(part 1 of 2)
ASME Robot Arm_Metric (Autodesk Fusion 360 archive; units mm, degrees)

design "ASME Robot Arm - Metric" references "Broached Hexagon Socket Head Cap Screw ASME B18.3.1M - M5x0.8 x 8 Steel Grade 2 Plain"
sketch "Sketch1" plane through (0, 0, 0) normal (0, 1, 0) x axis (1, 0, 0)
  line L1 (125, 0) -> (0, 0)
  line L2 (0, -40) -> (0, 0)
  line L3 (125, -15) -> (125, 0)
  line L4 (115, -15) -> (125, -15)
  line L5 (60, -45) -> (60, -40)
  curve K1 (115, -15) -> (60, -40)
  line L6 (55, -40) -> (60, -40)
  line L7 (55, -33) -> (55, -40)
  line L8 (54, -33) -> (55, -33)
  line L9 (54, -28) -> (54, -33)
  line L10 (55, -28) -> (54, -28)
  line L11 (55, -15.5519) -> (55, -28)
  line L12 (64, -8) -> (55, -15.5519)
  line L13 (64, 0) -> (64, -8)
  point P1 (0, 0)
  point P2 (0, 0)
  point P4 (0, 0)
  point P5 (0, -40)
  point P8 (60, -40)
  point P17 (64, 0)
  point P3 (125, 0)
  point P6 (125, -15)
  point P7 (115, -15)
  point P9 (60, -45)
  point P10 (55, -40)
  point P11 (55, -33)
  point P12 (54, -33)
  point P13 (54, -28)
  point P16 (64, -8)
  coincident P1 P2
  horizontal L1
  coincident P1 P4
  perpendicular L1 L2
  perpendicular L1 L3
  perpendicular L3 L4
  horizontal P5 P8
  perpendicular L5 L6
  perpendicular L6 L7
  perpendicular L7 L8
  perpendicular L8 L9
  perpendicular L9 L10
  perpendicular L4 L11
  coincident L1 P17
  perpendicular L1 L13
  collinear L7 L11
  dimension "d2" distance P4 P5 = 40
  dimension "d3" = 250
  dimension "d4" distance P3 P6 = 15
  dimension "d5" distance P6 P7 = 10
  dimension "d9" distance P8 P9 = 5
  dimension "d16" = 120
  dimension "d17" distance P8 P10 = 5
  dimension "d18" distance P10 P11 = 7
  dimension "d19" distance P12 P13 = 5
  dimension "d20" distance P16 P17 = 8
  dimension "d21" = 128
  dimension "d22" angle L12 L13 = 50
  dimension "d23" = 108
revolve "Revolve1" sketch "Sketch1" AlongAngle 360
sketch "Sketch2" plane through (0, 0, 40) normal (0, 0, 1) x axis (-1, 0, 0)
  line L1 (0, 100) -> (0, 0)
  circle C1 centre (0, 0) radius 30
  circle C2 centre (0, 0) radius 25
  circle C3 centre (0, 0) radius 60
  circle C4 centre (0, 0) radius 55
  point P2 (0, 0)
  point P3 (0, 100)
  vertical L1
  dimension "d8" distance P2 P3 = 100
hole "Hole1" HoleDiameter 9 TipAngle 118 CBDepth 33 CBDiameter 15
circular_pattern "C-Pattern1" TotalAngle 360
sketch "Sketch1" plane through (0, 0, 0) normal (1, 0, 0) x axis (0, 1, 0)
sketch "Sketch2" plane through (0, 0, 0) normal (1, 0, 0) x axis (0, 1, 0)
  line L1 (0, 225) -> (0, 0)
  line L2 (-55, 40) -> (55, 40)
  line L3 (-55, 181.6987) -> (-55, 40)
  curve K1 (-55, 145) -> (-70, 225)
  curve K2 (-53.2004, 137.205) -> (-56.7996, 152.795)
  curve K3 (-70, 217) -> (-70, 233)
  curve K4 (55, 145) -> (70, 225)
  curve K5 (70, 217) -> (70, 233)
  curve K6 (53.2004, 137.205) -> (56.7996, 152.795)
  line L4 (55, 145) -> (-55, 145)
  circle C1 centre (0, 225) radius 70
  point P1 (0, 0)
  point P2 (0, 0)
  point P3 (0, 225)
  point P6 (0, 225)
  point P5 (-55, 40)
  point P7 (-55, 40)
  point P8 (-55, 181.6987)
  point P9 (-70, 225)
  point P10 (-55, 145)
  point P15 (70, 225)
  point P16 (55, 145)
  point P11 (-56.7996, 152.795)
  point P19 (56.7996, 152.795)
  point P12 (-53.2004, 137.205)
  point P20 (53.2004, 137.205)
  point P13 (-70, 233)
  point P17 (70, 233)
  point P14 (-70, 217)
  point P18 (70, 217)
  coincident P1 P2
  vertical L1
  coincident P3 P6
  coincident P5 P7
  coincident C1 P8
  perpendicular L2 L3
  coincident C1 P9
  coincident L3 P10
  midpoint P10 K2
  midpoint P9 K3
  vertical K3
  horizontal P6 P9
  symmetric L1 P9 P15
  symmetric L1 P10 P16
  symmetric L1 P11 P19
  symmetric L1 P12 P20
  symmetric L1 P13 P17
  symmetric L1 P14 P18
  dimension "d24" distance P3 L2 = 185
  dimension "d25" diameter C1 = 140
  dimension "d26" distance P11 P12 = 16
  dimension "d27" distance P13 P14 = 16
  dimension "d28" distance P6 P10 = 80
  dimension "d31" angle L3 K2 = 13
extrude "Extrude1" new body sketch "Sketch2" profile of C1 K1 K4 L4 distance 130
work_plane "WorkPlane1" AlongDistance 5
sketch "Sketch3" plane through (0, 0, 45) normal (0, 0, 1) x axis (-1, 0, 0)
  circle C1 centre (0, 0) radius 60
  circle C2 centre (0, 0) radius 55
  circle C3 centre (0, 0) radius 60
loft "Loft1" sketch "Sketch3" Start TakeOff Angle 0
sketch "Sketch4" plane through (0, 0, 0) normal (0, 1, 0) x axis (1, 0, 0)
  line L1 (65, -295) -> (-65, -295)
  line L2 (30, -295) -> (-30, -295)
  line L3 (30, -153) -> (30, -295)
  line L4 (-30, -153) -> (30, -153)
  line L5 (-30, -295) -> (-30, -153)
  line L6 (0, -153) -> (0, -295)
  point P4 (-30, -295)
  point P8 (0, -295)
  point P9 (0, -153)
  point P6 (30, -153)
  point P7 (-30, -153)
  point P10 (65, -225)
  horizontal L2
  vertical L3
  horizontal L4
  vertical L5
  coincident L1 P4
  midpoint L1 P8
  midpoint L4 P9
  midpoint L1 L2
  dimension "d36" distance P6 P7 = 60
  dimension "d37" distance L4 P10 = 72
extrude "Extrude2" cut sketch "Sketch4" profile of L1 L2 L3 L4 L5 no distance stored
as_built_joint "As-built1" OffsetX 0 OffsetY 0 OffsetZ 0 AngleZ 0
sketch "Sketch1" plane through (0, 0, 0) normal (1, 0, 0) x axis (0, 1, 0)
  line L1 (0, 575) -> (0, 225)
  curve K1 (46.9846, 557.899) -> (63.4415, 254.5833)
  curve K2 (63.4408, 254.5848) -> (63.4423, 254.5817)
  curve K3 (48.4834, 566.399) -> (45.4858, 549.399)
  line L2 (46.9846, 557.899) -> (0, 575)
  line L3 (50, 575) -> (0, 575)
  line L4 (63.4415, 254.5833) -> (0, 225)
  curve K4 (-46.9846, 557.899) -> (-63.4415, 254.5833)
  curve K5 (-63.4408, 254.5848) -> (-63.4423, 254.5817)
  curve K6 (-48.4834, 566.399) -> (-45.4858, 549.399)
  line L5 (46.9846, 557.899) -> (-46.9846, 557.899)
  line L6 (63.4415, 254.5833) -> (-63.4415, 254.5833)
  arc A1 centre (0, 225) radius 70 clockwise from (-70, 225) to (70, 225)
  circle C1 centre (0, 225) radius 70
  circle C2 centre (0, 575) radius 50
  point P2 (70, 225)
  point P5 (0, 225)
  point P6 (0, 225)
  point P8 (63.4415, 254.5833)
  point P9 (46.9846, 557.899)
  point P14 (0, 575)
  point P15 (46.9846, 557.899)
  point P16 (0, 575)
  point P17 (0, 575)
  point P18 (50, 575)
  point P4 (0, 225)
  point P19 (0, 225)
  point P7 (0, 575)
  point P10 (63.4423, 254.5817)
  point P20 (-63.4415, 254.5833)
  point P21 (-46.9846, 557.899)
  point P22 (-63.4423, 254.5817)
  point P11 (63.4408, 254.5848)
  point P23 (-63.4408, 254.5848)
  point P12 (45.4858, 549.399)
  point P24 (-45.4858, 549.399)
  point P13 (48.4834, 566.399)
  point P25 (-48.4834, 566.399)
  concentric A1 C1
  coincident P2 C1
  coincident P5 P6
  vertical L1
  coincident A1 P8
  midpoint P8 K2
  midpoint P9 K3
  vertical P5 P14
  coincident C2 P15
  coincident P14 P16
  coincident P14 P17
  coincident C2 P18
  horizontal L3
  tangent C1 K2
  coincident P4 P19
  coincident P7 P14
  coincident P9 C2
  coincident K3 P15
  coincident A1 P10
  coincident C1 P10
  symmetric L1 P8 P20
  symmetric L1 P9 P21
  symmetric L1 P10 P22
  symmetric L1 P11 P23
  symmetric L1 P12 P24
  symmetric L1 P13 P25
  dimension "d50" diameter C2 = 100
  dimension "d51" distance P5 P14 = 350
  dimension "d52" angle L2 L3 = 20
  dimension "d54" angle L1 L4 = 65
  dimension "d55" angle K3 L3 = 80
  dimension "d56" distance P12 P13 = 17
extrude "Extrude1" new body sketch "Sketch1" profile of C1 distance 29
extrude "Extrude2" new body sketch "Sketch1" profile of C2 distance 45
split_face "SplitFace1"
split_face "SplitFace2"
sketch "Sketch2" plane through (0, 0, 0) normal (0, 1, 0) x axis (1, 0, 0)
  line L1 (29, -295) -> (-29, -295)
  line L2 (-22.5, -525) -> (22.5, -525)
  curve K1 (22.5, -525) -> (29, -295)
  line L3 (0, -557.2354) -> (0, -225)
  curve K2 (22.5, -547.5) -> (22.5, -502.5)
  curve K3 (29, -317.5) -> (29, -272.5)
  curve K4 (-22.5, -525) -> (-29, -295)
  curve K5 (-29, -317.5) -> (-29, -272.5)
  curve K6 (-22.5, -547.5) -> (-22.5, -502.5)
  point P3 (29, -295)
  point P6 (29, -295)
  point P4 (22.5, -525)
  point P7 (22.5, -525)
  point P8 (0, -225)
  point P9 (0, -225)
  point P15 (-29, -295)
  point P16 (-22.5, -525)
  point P11 (22.5, -502.5)
  point P19 (-22.5, -502.5)
  point P12 (22.5, -547.5)
  point P20 (-22.5, -547.5)
  point P13 (29, -272.5)
  point P17 (-29, -272.5)
  point P14 (29, -317.5)
  point P18 (-29, -317.5)
  coincident P3 P6
  coincident P4 P7
  coincident P8 P9
  perpendicular L2 L3
  midpoint P7 K2
  vertical K2
  midpoint P6 K3
  vertical K3
  symmetric P6 L3 P15
  symmetric P7 L3 P16
  symmetric L3 P11 P19
  symmetric L3 P12 P20
  symmetric L3 P13 P17
  symmetric L3 P14 P18
  dimension "d59" distance P11 P12 = 45
  dimension "d60" distance P13 P14 = 45
loft "Loft1"
as_built_joint "As-built2" OffsetX 0 OffsetY 0 OffsetZ 0 AngleZ 0 RotateMinimum -107 RotateMaximum 107
sketch "Sketch1" plane through (0, 0, 0) normal (1, 0, 0) x axis (0, 1, 0)
  line L1 (0, 925) -> (0, 575)
  line L2 (45.3154, 596.1309) -> (0, 575)
  line L3 (36.2222, 915.2943) -> (0, 925)
  curve K1 (36.2222, 915.2943) -> (45.3154, 596.1309)
  curve K2 (42.2511, 937.7943) -> (30.1934, 892.7943)
  curve K3 (34.8235, 618.6309) -> (55.8073, 573.6309)
  curve K4 (-36.2222, 915.2943) -> (-45.3154, 596.1309)
  curve K5 (-34.8235, 618.6309) -> (-55.8073, 573.6309)
  curve K6 (-42.2511, 937.7943) -> (-30.1934, 892.7943)
  line L4 (-45.3154, 596.1309) -> (45.3154, 596.1309)
  line L5 (-36.2222, 915.2943) -> (36.2222, 915.2943)
  arc A1 centre (0, 575) radius 50 clockwise from (-46.9846, 557.899) to (46.9846, 557.899)
  circle C1 centre (0, 575) radius 50
  circle C2 centre (0, 925) radius 37.5
  point P2 (46.9846, 557.899)
  point P4 (0, 575)
  point P7 (0, 575)
  point P6 (0, 925)
  point P8 (0, 925)
  point P9 (0, 575)
  point P10 (45.3154, 596.1309)
  point P11 (0, 925)
  point P12 (36.2222, 915.2943)
  point P17 (-45.3154, 596.1309)
  point P18 (-36.2222, 915.2943)
  point P13 (30.1934, 892.7943)
  point P21 (-30.1934, 892.7943)
  point P14 (42.2511, 937.7943)
  point P22 (-42.2511, 937.7943)
  point P15 (55.8073, 573.6309)
  point P19 (-55.8073, 573.6309)
  point P16 (34.8235, 618.6309)
  point P20 (-34.8235, 618.6309)
  point P5 (0, 575)
  concentric A1 C1
  coincident P2 C1
  coincident P4 P7
  coincident P6 P8
  vertical L1
  coincident P4 P9
  coincident C1 P10
  coincident P6 P11
  coincident C2 P12
  midpoint P12 K2
  midpoint P10 K3
  symmetric L1 P10 P17
  symmetric L1 P12 P18
  symmetric L1 P13 P21
  symmetric L1 P14 P22
  symmetric L1 P15 P19
  symmetric L1 P16 P20
  tangent C1 K3
  tangent C2 K2
  dimension "d65" diameter C2 = 75
  dimension "d66" distance P5 P6 = 350
  dimension "d67" angle L1 L2 = 65
  dimension "d68" angle L1 L3 = 75
  dimension "d71" distance P13 P14 = 45
  dimension "d72" distance P15 P16 = 45
extrude "Extrude1" new body sketch "Sketch1" profile of C1 L4 distance 100
extrude "Extrude2" new body sketch "Sketch1" profile of C2 L5 distance 80
sketch "Sketch2" plane through (0, 0, 0) normal (0, 1, 0) x axis (1, 0, 0)
  line L1 (-50, -625) -> (-50, -525)
  line L2 (-40, -962.5) -> (-40, -887.5)
  curve K1 (-40, -887.5) -> (-50, -625)
  curve K2 (-40, -915) -> (-40, -860)
  curve K3 (-50, -652.5) -> (-50, -597.5)
  line L3 (0, -911.4032) -> (0, -575)
  curve K4 (40, -887.5) -> (50, -625)
  curve K5 (50, -652.5) -> (50, -597.5)
  curve K6 (40, -915) -> (40, -860)
  line L4 (0, -915.2943) -> (0, -596.1309)
  point P3 (-50, -625)
  point P6 (-50, -625)
  point P4 (-40, -887.5)
  point P7 (-40, -887.5)
  point P12 (0, -575)
  point P13 (0, -575)
  point P15 (50, -625)
  point P16 (40, -887.5)
  point P8 (-40, -860)
  point P19 (40, -860)
  point P9 (-40, -915)
  point P20 (40, -915)
  point P10 (-50, -597.5)
  point P17 (50, -597.5)
  point P11 (-50, -652.5)
  point P18 (50, -652.5)
  coincident P3 P6
  coincident P4 P7
  midpoint P7 K2
  midpoint P6 K3
  coincident P12 P13
  vertical L3
  symmetric P6 L3 P15
  symmetric P7 L3 P16
  symmetric P8 L3 P19
  symmetric P9 L3 P20
  symmetric P10 L3 P17
  symmetric P11 L3 P18
  vertical K3
  vertical K2
  dimension "d77" distance P8 P9 = 55
  dimension "d78" distance P10 P11 = 55
split_face "SplitFace1"
split_face "SplitFace2"
work_plane "WorkPlane1" RotateAngle 0
work_plane "WorkPlane2" AlongDistance 40
sketch "Sketch4" plane through (0, 0, 847.5) normal (0, 0, -1) x axis (-1, 0, 0)
  circle C1 centre (0, 0) radius 42.5
  point P1 (0, 0)
  point P2 (0, 0)
  coincident P1 P2
  dimension "d92" diameter C1 = 85
loft "Loft2" sketch "Sketch4"
sketch "Sketch1" plane through (0, 0, 0) normal (1, 0, 0) x axis (0, 1, 0)
  line L1 (0, 925) -> (0, 575)
  line L2 (45.3154, 596.1309) -> (0, 575)
  line L3 (36.2222, 915.2943) -> (0, 925)
  curve K1 (36.2222, 915.2943) -> (45.3154, 596.1309)
  curve K2 (42.2511, 937.7943) -> (30.1934, 892.7943)
  curve K3 (37.1261, 618.6309) -> (53.5047, 573.6309)
  curve K4 (-36.2222, 915.2943) -> (-45.3154, 596.1309)
  curve K5 (-37.1261, 618.6309) -> (-53.5047, 573.6309)
  curve K6 (-42.2511, 937.7943) -> (-30.1934, 892.7943)
  line L4 (-45.3154, 596.1309) -> (45.3154, 596.1309)
  line L5 (-36.2222, 915.2943) -> (36.2222, 915.2943)
  arc A1 centre (0, 575) radius 50 clockwise from (-46.9846, 557.899) to (46.9846, 557.899)
  circle C1 centre (0, 575) radius 50
  circle C2 centre (0, 925) radius 37.5
  point P2 (46.9846, 557.899)
  point P4 (0, 575)
  point P7 (0, 575)
  point P6 (0, 925)
  point P8 (0, 925)
  point P9 (0, 575)
  point P10 (45.3154, 596.1309)
  point P11 (0, 925)
  point P12 (36.2222, 915.2943)
  point P17 (-45.3154, 596.1309)
  point P18 (-36.2222, 915.2943)
  point P13 (30.1934, 892.7943)
  point P21 (-30.1934, 892.7943)
  point P14 (42.2511, 937.7943)
  point P22 (-42.2511, 937.7943)
  point P15 (53.5047, 573.6309)
  point P19 (-53.5047, 573.6309)
  point P16 (37.1261, 618.6309)
  point P20 (-37.1261, 618.6309)
  point P5 (0, 575)
  concentric A1 C1
  coincident P2 C1
  coincident P4 P7
  coincident P6 P8
  vertical L1
  coincident P4 P9
  coincident C1 P10
  coincident P6 P11
  coincident C2 P12
  midpoint P12 K2
  midpoint P10 K3
  symmetric L1 P10 P17
  symmetric L1 P12 P18
  symmetric L1 P13 P21
  symmetric L1 P14 P22
  symmetric L1 P15 P19
  symmetric L1 P16 P20
  dimension "d65_1" diameter C2 = 75
  dimension "d66_1" distance P5 P6 = 350
  dimension "d67_1" angle L1 L2 = 65
  dimension "d68_1" angle L1 L3 = 75
  dimension "d69_1" angle L2 K3 = 85
  dimension "d70_1" angle L1 K2 = 15
  dimension "d71_1" distance P13 P14 = 45
  dimension "d72_1" distance P15 P16 = 45
extrude "Extrude1" new body sketch "Sketch1" profile of C1 L4 distance 100 named "d73_1"
extrude "Extrude2" new body sketch "Sketch1" profile of C2 L5 distance 80 named "d75_1"
sketch "Sketch2" plane through (0, 0, 0) normal (0, 1, 0) x axis (1, 0, 0)
  line L1 (-50, -625) -> (-50, -525)
  line L2 (-40, -962.5) -> (-40, -887.5)
  curve K1 (-40, -887.5) -> (-50, -625)
  curve K2 (-47.1175, -914.063) -> (-32.8825, -860.937)
  curve K3 (-42.8825, -651.563) -> (-57.1175, -598.437)
  line L3 (0, -911.4032) -> (0, -575)
  curve K4 (40, -887.5) -> (50, -625)
  curve K5 (42.8825, -651.563) -> (57.1175, -598.437)
  curve K6 (47.1175, -914.063) -> (32.8825, -860.937)
  line L4 (0, -915.2943) -> (0, -596.1309)
  point P3 (-50, -625)
  point P6 (-50, -625)
  point P4 (-40, -887.5)
  point P7 (-40, -887.5)
  point P12 (0, -575)
  point P13 (0, -575)
  point P15 (50, -625)
  point P16 (40, -887.5)
  point P8 (-32.8825, -860.937)
  point P19 (32.8825, -860.937)
  point P9 (-47.1175, -914.063)
  point P20 (47.1175, -914.063)
  point P10 (-57.1175, -598.437)
  point P17 (57.1175, -598.437)
  point P11 (-42.8825, -651.563)
  point P18 (42.8825, -651.563)
  coincident P3 P6
  coincident P4 P7
  midpoint P7 K2
  midpoint P6 K3
  coincident P12 P13
  vertical L3
  symmetric P6 L3 P15
  symmetric P7 L3 P16
  symmetric P8 L3 P19
  symmetric P9 L3 P20
  symmetric P10 L3 P17
  symmetric P11 L3 P18
  dimension "d77_1" distance P8 P9 = 55
  dimension "d78_1" distance P10 P11 = 55
  dimension "d79_1" angle K3 L4 = 15
  dimension "d80_1" angle K2 L4 = 15
split_face "SplitFace1"
split_face "SplitFace2"
work_plane "WorkPlane1" RotateAngle 0 named "d91_1"
work_plane "WorkPlane2" AlongDistance 40 named "d93_1"
sketch "Sketch4" plane through (0, 0, 847.5) normal (0, 0, -1) x axis (-1, 0, 0)
  circle C1 centre (0, 0) radius 42.5
  point P1 (0, 0)
  point P2 (0, 0)
  coincident P1 P2
  dimension "d92_1" diameter C1 = 85
extrude "Extrude4" new body sketch "Sketch4" against normal blind 5
loft "Loft2"
loft "Loft1"
sketch "Sketch3" plane through (0, 0, 0) normal (0, 1, 0) x axis (1, 0, 0)
  line L1 (-50, -525) -> (50, -525)
  line L2 (40, -962.5) -> (-40, -962.5)
  line L3 (-23, -525) -> (23, -525)
  line L4 (-23, -630) -> (-23, -525)
  line L5 (23, -630) -> (-23, -630)
  line L6 (23, -525) -> (23, -630)
  line L7 (-19, -962.5) -> (19, -962.5)
  line L8 (-19, -886.5) -> (-19, -962.5)
  line L9 (19, -886.5) -> (-19, -886.5)
  line L10 (19, -962.5) -> (19, -886.5)
  point P6 (23, -525)
  point P10 (19, -962.5)
  point P8 (-23, -630)
  point P9 (23, -630)
  point P7 (-23, -525)
  point P11 (-19, -962.5)
  point P12 (-19, -886.5)
  horizontal L3
  vertical L4
  horizontal L5
  vertical L6
  coincident L1 P6
  midpoint L1 L3
  horizontal L7
  vertical L8
  horizontal L9
  vertical L10
  coincident L2 P10
  midpoint L2 L7
  dimension "d81" distance P8 P9 = 46
  dimension "d82" distance P7 P8 = 105
  dimension "d83" distance P10 P11 = 38
  dimension "d84" distance P11 P12 = 76
extrude "Extrude3" cut sketch "Sketch3" distance 150
remove_body "RemoveBody1"
as_built_joint "As-built3" OffsetX 0 OffsetY 0 OffsetZ 0 AngleZ 0 RotateMinimum -105 RotateMaximum 105
sketch "Sketch3" plane through (0, 0, 0) normal (0, 1, 0) x axis (1, 0, 0)
  line L1 (-50, -525) -> (50, -525)
  line L2 (40, -962.5) -> (-40, -962.5)
  line L3 (-23, -525) -> (23, -525)
  line L4 (-23, -630) -> (-23, -525)
  line L5 (23, -630) -> (-23, -630)
  line L6 (23, -525) -> (23, -630)
  line L7 (-19, -962.5) -> (19, -962.5)
  line L8 (-19, -886.5) -> (-19, -962.5)
  line L9 (19, -886.5) -> (-19, -886.5)
  line L10 (19, -962.5) -> (19, -886.5)
  point P6 (23, -525)
  point P10 (19, -962.5)
  point P8 (-23, -630)
  point P9 (23, -630)
  point P7 (-23, -525)
  point P11 (-19, -962.5)
  point P12 (-19, -886.5)
  horizontal L3
  vertical L4
  horizontal L5
  vertical L6
  coincident L1 P6
  midpoint L1 L3
  horizontal L7
  vertical L8
  horizontal L9
  vertical L10
  coincident L2 P10
  midpoint L2 L7
  dimension "d81_1" distance P8 P9 = 46
  dimension "d82_1" distance P7 P8 = 105
  dimension "d83_1" distance P10 P11 = 38
  dimension "d84_1" distance P11 P12 = 76
extrude "Extrude5" cut sketch "Sketch3" profile of L2 L7 L8 L9 L10 no distance stored
remove_body "RemoveBody1"
as_built_joint "As-built4" OffsetX 0 OffsetY 0 OffsetZ 0 AngleZ 0
sketch "Sketch1" plane through (0, 0, 0) normal (1, 0, 0) x axis (0, 1, 0)
  line L1 (-35.2385, 937.8258) -> (35.2385, 937.8258)
  line L2 (-35.2385, 937.8258) -> (0, 925)
  line L3 (0, 962.5) -> (0, 925)
  arc A1 centre (0, 925) radius 37.5 clockwise from (-36.2222, 915.2943) to (36.2222, 915.2943)
  circle C1 centre (0, 925) radius 37.5
  point P3 (-36.2222, 915.2943)
  point P6 (35.2385, 937.8258)
  point P7 (-35.2385, 937.8258)
  point P5 (0, 925)
  point P8 (0, 925)
  point P9 (-35.2385, 937.8258)
  point P10 (0, 925)
  point P11 (0, 962.5)
  concentric A1 C1
  coincident P3 C1
  coincident A1 P6
  coincident C1 P7
  horizontal L1
  coincident P5 P8
  coincident P7 P9
  coincident P5 P10
  midpoint A1 P11
  dimension "d109" angle L2 L3 = 70
extrude "Extrude1" new body sketch "Sketch1" profile of A1 C1 L1 distance 37.5
work_plane "WorkPlane1" RotateAngle 0
work_plane "WorkPlane2" AlongDistance 50
sketch "Sketch2" plane through (0, 0, 1012.5) normal (0, 0, 1) x axis (1, 0, 0)
  circle C1 centre (0, 0) radius 50
  point P1 (0, 0)
  point P2 (0, 0)
  coincident P1 P2
  dimension "d106" diameter C1 = 100
extrude "Extrude2" new body sketch "Sketch2" along normal blind 10
split_face "SplitFace1"
sketch "Sketch3" plane through (0, 0, 0) normal (0, 1, 0) x axis (1, 0, 0)
  line L1 (-18.75, -962.5) -> (-18.75, -937.8258)
  line L2 (0, -1012.5) -> (0, 0)
  line L3 (50, -1012.5) -> (-50, -1012.5)
  curve K1 (-50, -1012.5) -> (-18.75, -962.5)
  curve K2 (-51.6246, -1017.5) -> (-48.3754, -1007.5)
  curve K3 (-21.9992, -972.5) -> (-15.5008, -952.5)
  curve K4 (50, -1012.5) -> (18.75, -962.5)
  curve K5 (21.9992, -972.5) -> (15.5008, -952.5)
  curve K6 (51.6246, -1017.5) -> (48.3754, -1007.5)
  point P1 (0, 0)
  point P4 (0, 0)
  point P5 (0, -1012.5)
  point P3 (-18.75, -962.5)
  point P8 (-18.75, -962.5)
  point P6 (-50, -1012.5)
  point P9 (-50, -1012.5)
  point P14 (18.75, -962.5)
  point P15 (50, -1012.5)
  point P10 (-48.3754, -1007.5)
  point P18 (48.3754, -1007.5)
  point P11 (-51.6246, -1017.5)
  point P19 (51.6246, -1017.5)
  point P12 (-15.5008, -952.5)
  point P16 (15.5008, -952.5)
  point P13 (-21.9992, -972.5)
  point P17 (21.9992, -972.5)
  coincident P1 P4
  parallel L1 L2
  midpoint P5 L3
  coincident P3 P8
  coincident P6 P9
  midpoint P9 K2
  midpoint P8 K3
  parallel K2 K3
  symmetric L2 P8 P14
  symmetric L2 P9 P15
  symmetric L2 P10 P18
  symmetric L2 P11 P19
  symmetric L2 P12 P16
  symmetric L2 P13 P17
  dimension "d110" angle L2 K3 = 18
  dimension "d111" distance P12 P13 = 20
  dimension "d112" distance P10 P11 = 10
sketch "Sketch4" plane through (0, 0, 0) normal (1, 0, 0) x axis (0, 1, 0)
  line L1 (-50, 1012.5) -> (50, 1012.5)
  curve K1 (50, 1012.5) -> (35.2385, 937.8258)
  curve K2 (35.2385, 945.3258) -> (35.2385, 930.3258)
  curve K3 (53.4973, 1020) -> (46.5027, 1005)
  line L2 (0, 1012.5) -> (0, 962.5)
  line L3 (0, 1012.5) -> (0, 0)
  curve K4 (-50, 1012.5) -> (-35.2385, 937.8258)
  curve K5 (-35.2385, 945.3258) -> (-35.2385, 930.3258)
  curve K6 (-53.4973, 1020) -> (-46.5027, 1005)
  arc A1 centre (0, 925) radius 37.5 clockwise from (-36.2222, 915.2943) to (36.2222, 915.2943)
  point P5 (50, 1012.5)
  point P8 (50, 1012.5)
  point P7 (35.2385, 937.8258)
  point P17 (-35.2385, 937.8258)
  point P18 (-50, 1012.5)
  point P9 (35.2385, 930.3258)
  point P19 (-35.2385, 930.3258)
  point P10 (35.2385, 945.3258)
  point P20 (-35.2385, 945.3258)
  point P11 (46.5027, 1005)
  point P21 (-46.5027, 1005)
  point P12 (53.4973, 1020)
  point P22 (-53.4973, 1020)
  point P23 (35.2385, 937.8258)
  coincident P5 P8
  midpoint P7 K2
  vertical K2
  midpoint P8 K3
  symmetric P7 L3 P17
  symmetric P8 L3 P18
  symmetric P9 L3 P19
  symmetric P10 L3 P20
  symmetric P11 L3 P21
  symmetric P12 L3 P22
  coincident P7 P23
  dimension "d113" angle K3 L2 = 25
  dimension "d115" distance P11 P12 = 15
  dimension "d116" distance P9 P10 = 15
loft "Loft1"
as_built_joint "As-built5" OffsetX 0 OffsetY 0 OffsetZ 0 AngleZ 0 RotateMinimum -92 RotateMaximum 92
sketch "Sketch1" plane through (0, 0, 0) normal (0, 1, 0) x axis (1, 0, 0)
  line L1 (50, -1022.5) -> (-50, -1022.5)
  line L2 (0, -1035.5) -> (0, -1020.5)
  line L3 (-50, -1032.5) -> (-50, -1022.5)
  line L4 (-34, -1032.5) -> (-50, -1032.5)
  line L5 (-34, -1031.5) -> (-34, -1032.5)
  line L6 (-31, -1031.5) -> (-34, -1031.5)
  line L7 (-31, -1032.5) -> (-31, -1031.5)
  line L8 (-27.5, -1032.5) -> (-31, -1032.5)
  line L9 (-27.5, -1035.5) -> (-27.5, -1032.5)
  line L10 (0, -1035.5) -> (-27.5, -1035.5)
  line L11 (-27.5, -1022.5) -> (-50, -1022.5)
  line L12 (-27.5, -1020.5) -> (-27.5, -1022.5)
  line L13 (0, -1020.5) -> (-27.5, -1020.5)
  point P8 (-34, -1032.5)
  point P2 (-50, -1022.5)
  point P6 (-50, -1022.5)
  point P14 (-50, -1022.5)
  point P15 (-27.5, -1022.5)
  point P4 (0, -1020.5)
  point P17 (0, -1020.5)
  point P18 (0, -1022.5)
  point P12 (-27.5, -1032.5)
  point P5 (0, -1035.5)
  point P9 (-34, -1031.5)
  point P10 (-31, -1031.5)
  point P16 (-27.5, -1020.5)
  perpendicular L1 L2
  perpendicular L1 L3
  perpendicular L3 L4
  perpendicular L4 L5
  perpendicular L5 L6
  perpendicular L6 L7
  perpendicular L5 L8
  perpendicular L8 L9
  perpendicular L2 L10
  coincident P8 L8
  coincident P2 L3
  coincident P2 P6
  coincident P2 P14
  coincident L1 P15
  perpendicular L3 L11
  perpendicular L1 L12
  perpendicular L12 L13
  coincident P4 P17
  midpoint L1 P18
  coincident L2 P18
  coincident P12 L12
  dimension "d121" distance P4 P5 = 15
  dimension "d123" distance P9 P10 = 3
  dimension "d124" distance P8 P9 = 1
  dimension "d125" = 62
  dimension "d126" = 55
  dimension "d167" distance L1 L4 = 10
  dimension "d169" distance P15 P16 = 2
revolve "Revolve1" sketch "Sketch1" AlongAngle 360
sketch "Sketch2" plane through (0, 0, 1032.5) normal (0, 0, 1) x axis (-1, 0, 0)
  line L1 (0, 41) -> (0, 0)
  circle C1 centre (0, 0) radius 34
  circle C2 centre (0, 0) radius 50
  point P2 (0, 0)
  point P3 (0, 0)
  point P4 (0, 41)
  coincident P2 P3
  vertical L1
  dimension "d128" distance P3 P4 = 41
hole "Hole1" HoleDepth 20 HoleDiameter 5.5 TipAngle 180 CBDepth 5 CBDiameter 10
circular_pattern "C-Pattern1" TotalAngle 360
sketch "Sketch3" plane through (0, 0, 1035.5) normal (0, 0, 1) x axis (-1, 0, 0)
  line L1 (0, 20) -> (0, 0)
  line L2 (8.4853, 8.4853) -> (0, 0)
  line L3 (10, 0) -> (0, 0)
  circle C1 centre (0, 0) radius 27.5
  point P2 (0, 0)
  point P3 (0, 0)
  point P5 (0, 0)
  point P4 (0, 20)
  point P6 (8.4853, 8.4853)
  coincident P2 P3
  vertical L1
  horizontal L3
  coincident P2 P5
  dimension "d136" distance P3 P4 = 20
  dimension "d137" distance P5 P6 = 12
  dimension "d138" angle L2 L3 = 45
hole "Hole1" HoleDepth 20 HoleDiameter 4.234 TipAngle 180
circular_pattern "C-Pattern2" TotalAngle 360
hole "Hole2" HoleDepth 20 HoleDiameter 4.234 TipAngle 180
as_built_joint "As-built6" OffsetX 0 OffsetY 0 OffsetZ 0 AngleZ 0
extrude "Extrude3" add of existing geometry to an object
sketch "Sketch5" plane through (0, 0, 0) normal (0, 1, 0) x axis (1, 0, 0)
  line L1 (0, -1022.5) -> (0, -1017.5)
  line L2 (-50, -1022.5) -> (50, -1022.5)
  line L3 (27.55, -1017.5) -> (0, -1017.5)
  line L4 (27.55, -1022.5) -> (27.55, -1017.5)
  line L5 (0, -1022.5) -> (27.55, -1022.5)
  point P3 (0, -1022.5)
  point P7 (27.55, -1022.5)
  point P2 (0, -1017.5)
  vertical L1
  midpoint P3 L2
  perpendicular L1 L3
  coincident L2 P7
  perpendicular L2 L4
  dimension "d170" distance P2 P3 = 5
  dimension "d171" = 55.1
revolve "Revolve1" sketch "Sketch5" AlongAngle 360
sketch "Sketch6" plane through (0, 0, 1022.5) normal (0, 0, 1) x axis (-1, 0, 0)
  circle C1 centre (0, 0) radius 27.55
  circle C2 centre (0, 0) radius 50
  circle C3 centre (0, 41) radius 2.75
hole "Hole3" HoleDepth 15 HoleDiameter 4.234 TipAngle 180
circular_pattern "C-Pattern1" TotalAngle 360
chamfer "Chamfer1" distance 3 distance 1 distance 0.5
fillet "Fillet1" radius 3
fillet "Fillet2" radius 35
fillet "Fillet1" radius 8 15
fillet "Fillet1" radius 200 10
sketch "Sketch3" plane through (0, 0, 0) normal (1, 0, 0) x axis (0, 1, 0)
  line L1 (0, 490) -> (0, 340)
  curve K1 (24.1481, 483.5295) -> (33.8074, 349.0587)
  line L2 (33.8074, 349.0587) -> (0, 340)
  curve K2 (24.8557, 497.0295) -> (23.4406, 470.0295)
  line L3 (24.1481, 483.5295) -> (0, 490)
  curve K3 (-24.1481, 483.5295) -> (-33.8074, 349.0587)
  curve K4 (32.2112, 362.0587) -> (35.4036, 336.0587)
  curve K5 (-32.2112, 362.0587) -> (-35.4036, 336.0587)
  curve K6 (-24.8557, 497.0295) -> (-23.4406, 470.0295)
  circle C1 centre (0, 490) radius 25
  circle C2 centre (0, 340) radius 35
  arc A1 centre (0, 225) radius 70 clockwise from (-70, 225) to (70, 225)
  point P3 (0, 340)
  point P4 (0, 340)
  point P2 (0, 490)
  point P5 (0, 490)
  point P1 (0, 0)
  point P9 (33.8074, 349.0587)
  point P10 (24.1481, 483.5295)
  point P11 (0, 340)
  point P14 (0, 490)
  point P15 (-33.8074, 349.0587)
  point P16 (-24.1481, 483.5295)
  point P12 (23.4406, 470.0295)
  point P21 (-23.4406, 470.0295)
  point P13 (24.8557, 497.0295)
  point P22 (-24.8557, 497.0295)
  point P17 (35.4036, 336.0587)
  point P19 (-35.4036, 336.0587)
  point P18 (32.2112, 362.0587)
  point P20 (-32.2112, 362.0587)
  point P8 (0, 225)
  coincident P3 P4
  coincident P2 P5
  vertical L1
  coincident P1 L1
  coincident C2 P9
  coincident C1 P10
  coincident P3 P11
  midpoint P10 K2
  coincident P2 P14
  midpoint P9 K4
  symmetric L1 P9 P15
  symmetric L1 P10 P16
  symmetric L1 P12 P21
  symmetric L1 P13 P22
  symmetric L1 P17 P19
  symmetric L1 P18 P20
  dimension "d196" diameter C2 = 70
  dimension "d197" diameter C1 = 50
  dimension "d198" distance P3 P8 = 115
  dimension "d199" distance P4 P5 = 150
  dimension "d200" angle L1 L2 = 75
  dimension "d201" angle L1 L3 = 75
  dimension "d202" angle L1 K2 = 3
  dimension "d203" angle L1 K4 = 7
  dimension "d204" distance P17 P18 = 26
  dimension "d205" distance P12 P13 = 27
extrude "Extrude3" sketch "Sketch3" profile of C1 C2 K1 K3 blind 5
mirror "Mirror1" mirrorStitchTolerance 0.1
fillet "Fillet2" radius 120
chamfer "Chamfer1" distance 2
sketch "Sketch5" plane through (65, 0, 0) normal (1, 0, 0) x axis (0, 1, 0)
  curve K1 (39.6152, 145) -> (40.3844, 148.3743)
  curve K2 (40.3844, 148.3743) -> (55, 225)
  curve K3 (-55, 225) -> (-40.3844, 148.3743)
  curve K4 (-40.3844, 148.3743) -> (-39.6152, 145)
  line L1 (39.6152, 145) -> (-39.6152, 145)
  arc A1 centre (0, 225) radius 55 clockwise from (-55, 225) to (55, 225)
  arc A2 centre (0, 225) radius 55 clockwise from (-55, 225) to (55, 225)
  circle C1 centre (0, 225) radius 55
  point P10 (-55, 225)
  concentric A2 C1
  coincident P10 C1
work_plane "WorkPlane2" sketch "Sketch5" AlongDistance 6
sketch "Sketch6" plane through (71, 0, 0) normal (1, 0, 0) x axis (0, 1, 0)
loft "Loft2" sketch "Sketch5"
mirror "Mirror1" mirrorStitchTolerance 0.1
fillet "Fillet1" radius 10
fillet "Fillet2" radius 100
fillet "Fillet3" radius 10
fillet "Fillet2" radius 10
fillet "Fillet4" radius 10
work_plane "WorkPlane3" AlongDistance 5
sketch "Sketch5" plane through (55, 0, 0) normal (1, 0, 0) x axis (0, 1, 0)
  arc A1 centre (0, 575) radius 50 clockwise from (45.6932, 595.3011) to (-45.6932, 595.3011)
loft "Loft3"
mirror "Mirror1" mirrorStitchTolerance 0.1
fillet "Fillet5" radius 50
fillet "Fillet4" radius 5
sketch "Sketch7" plane through (0, 0, 0) normal (1, 0, 0) x axis (0, 1, 0)
  line L1 (4.1989, 228.3433) -> (-19.0632, 190.9471)
  line L2 (4.1989, 247.7426) -> (4.1989, 228.3433)
  line L3 (-8.9006, 229.9785) -> (2.1114, 248.3458)
  curve K1 (-12.1232, 228.3672) -> (-8.9006, 229.9785)
  line L4 (-19.0632, 228.3486) -> (-12.1232, 228.3672)
  line L5 (-19.0632, 251.6902) -> (-19.0632, 228.3486)
  line L6 (21.2698, 251.6902) -> (-19.0632, 251.6902)
  line L7 (22.7039, 227.9253) -> (22.7039, 250.1979)
  line L8 (-0.4577, 190.6191) -> (22.7039, 227.9253)
  line L9 (-19.0632, 190.6191) -> (-0.4577, 190.6191)
  line L10 (-19.0632, 190.9471) -> (-19.0632, 190.6191)
  line L11 (17.8557, 598.5641) -> (-14.4108, 598.5641)
  line L12 (-14.4108, 549.7072) -> (0.4736, 549.7072)
  line L13 (-14.4108, 549.9697) -> (-14.4108, 549.7072)
  line L14 (19.0029, 579.5522) -> (19.0029, 597.3703)
  line L15 (-14.4108, 579.8909) -> (-8.8588, 579.9057)
  line L16 (-6.2807, 581.1948) -> (2.5289, 595.8887)
  line L17 (4.1989, 595.4061) -> (4.1989, 579.8867)
  line L18 (4.1989, 579.8867) -> (-14.4108, 549.9697)
  line L19 (0.4736, 549.7072) -> (19.0029, 579.5522)
  line L20 (-14.4108, 598.5641) -> (-14.4108, 579.8909)
  curve K2 (-8.8588, 579.9057) -> (-6.2807, 581.1948)
  curve K3 (-7.553, 924.1916) -> (-5.2327, 925.3517)
  line L21 (-12.5498, 940.9841) -> (-12.5498, 924.1782)
  line L22 (-12.5498, 924.1782) -> (-7.553, 924.1916)
  line L23 (-12.5498, 897.2492) -> (-12.5498, 897.0129)
  line L24 (4.1989, 938.1419) -> (4.1989, 924.1744)
  line L25 (17.5225, 923.8734) -> (17.5225, 939.9097)
  line L26 (0.8461, 897.0129) -> (17.5225, 923.8734)
  line L27 (4.1989, 924.1744) -> (-12.5498, 897.2492)
  line L28 (16.49, 940.9841) -> (-12.5498, 940.9841)
  line L29 (-5.2327, 925.3517) -> (2.6959, 938.5762)
  line L30 (-12.5498, 897.0129) -> (0.8461, 897.0129)
  arc A1 centre (3.0665, 247.7426) radius 1.1324 clockwise from (3.0639, 248.875) to (4.1989, 247.7426)
  arc A2 centre (2.9857, 247.8939) radius 0.9843 clockwise from (2.1114, 248.3458) to (3.0639, 248.875)
  arc A3 centre (21.2738, 250.2588) radius 1.4314 clockwise from (21.2698, 251.6902) to (22.7039, 250.1979)
  arc A4 centre (3.2283, 595.5271) radius 0.7874 clockwise from (2.5289, 595.8887) to (3.2909, 596.312)
  arc A5 centre (3.293, 595.4061) radius 0.9059 clockwise from (3.2909, 596.312) to (4.1989, 595.4061)
  arc A6 centre (17.8588, 597.419) radius 1.1451 clockwise from (17.8557, 598.5641) to (19.0029, 597.3703)
  arc A7 centre (16.4928, 939.9535) radius 1.0306 clockwise from (16.49, 940.9841) to (17.5225, 939.9097)
  arc A8 centre (3.3254, 938.2508) radius 0.7087 clockwise from (2.6959, 938.5762) to (3.3817, 938.9572)
  arc A9 centre (3.3836, 938.1419) radius 0.8153 clockwise from (3.3817, 938.9572) to (4.1989, 938.1419)
emboss "Emboss1" sketch "Sketch7" Depth -2 Horizontal Distance 0 Vertical Distance 0 Rotation Angle 0
emboss "Emboss1" sketch "Sketch7" Depth -2 Horizontal Distance 0 Vertical Distance 0 Rotation Angle 0
emboss "Emboss1" sketch "Sketch7" Depth -2 Horizontal Distance 0 Vertical Distance 0 Rotation Angle 0
sketch "Sketch8" plane through (0, 0, 0) normal (1, 0, 0) x axis (0, 1, 0)
  line L1 (4.3387, 213.8621) -> (-18.9234, 251.2583)
  line L2 (4.3387, 194.4628) -> (4.3387, 213.8621)
  line L3 (-8.7608, 212.2269) -> (2.2512, 193.8596)
  curve K1 (-11.9834, 213.8382) -> (-8.7608, 212.2269)
  line L4 (-18.9234, 213.8568) -> (-11.9834, 213.8382)
  line L5 (-18.9234, 190.5152) -> (-18.9234, 213.8568)
  line L6 (21.4097, 190.5152) -> (-18.9234, 190.5152)
  line L7 (22.8437, 214.2801) -> (22.8437, 192.0075)
  line L8 (-0.3179, 251.5863) -> (22.8437, 214.2801)
  line L9 (-18.9234, 251.5863) -> (-0.3179, 251.5863)
  line L10 (-18.9234, 251.2583) -> (-18.9234, 251.5863)
  line L11 (-14.271, 568.4323) -> (-8.719, 568.4175)
  line L12 (19.1427, 568.771) -> (19.1427, 550.9529)
  line L13 (-14.271, 598.616) -> (0.6134, 598.616)
  line L14 (4.3387, 568.4365) -> (-14.271, 598.3535)
  line L15 (-6.1409, 567.1284) -> (2.6687, 552.4345)
  line L16 (-14.271, 598.3535) -> (-14.271, 598.616)
  line L17 (0.6134, 598.616) -> (19.1427, 568.771)
  curve K2 (-8.719, 568.4175) -> (-6.1409, 567.1284)
  line L18 (17.9955, 549.7591) -> (-14.271, 549.7591)
  line L19 (-14.271, 549.7591) -> (-14.271, 568.4323)
  line L20 (4.3387, 552.9171) -> (4.3387, 568.4365)
  line L21 (-12.41, 940.9591) -> (0.9859, 940.9591)
  line L22 (17.6623, 914.0986) -> (17.6623, 898.0623)
  line L23 (-12.41, 940.7228) -> (-12.41, 940.9591)
  line L24 (0.9859, 940.9591) -> (17.6623, 914.0986)
  line L25 (-5.0929, 912.6203) -> (2.8357, 899.3958)
  curve K3 (-7.4132, 913.7804) -> (-5.0929, 912.6203)
  line L26 (-12.41, 913.7938) -> (-7.4132, 913.7804)
  line L27 (4.3387, 899.8301) -> (4.3387, 913.7976)
  line L28 (4.3387, 913.7976) -> (-12.41, 940.7228)
  line L29 (16.6298, 896.9879) -> (-12.41, 896.9879)
  line L30 (-12.41, 896.9879) -> (-12.41, 913.7938)
  arc A1 centre (3.2063, 194.4628) radius 1.1324 between (3.2037, 193.3304) and (4.3387, 194.4628)
  arc A2 centre (3.1255, 194.3115) radius 0.9843 between (2.2512, 193.8596) and (3.2037, 193.3304)
  arc A3 centre (21.4136, 191.9466) radius 1.4314 between (21.4097, 190.5152) and (22.8437, 192.0075)
  arc A4 centre (3.4328, 552.9171) radius 0.9059 between (3.4307, 552.0112) and (4.3387, 552.9171)
  arc A5 centre (3.3682, 552.7961) radius 0.7874 between (2.6687, 552.4345) and (3.4307, 552.0112)
  arc A6 centre (17.9986, 550.9042) radius 1.1451 between (17.9955, 549.7591) and (19.1427, 550.9529)
  arc A7 centre (16.6326, 898.0185) radius 1.0306 between (16.6298, 896.9879) and (17.6623, 898.0623)
  arc A8 centre (3.4652, 899.7212) radius 0.7087 between (2.8357, 899.3958) and (3.5215, 899.0148)
  arc A9 centre (3.5234, 899.8301) radius 0.8153 between (3.5215, 899.0148) and (4.3387, 899.8301)
emboss "Emboss2" sketch "Sketch8" Depth -2 Horizontal Distance 0 Vertical Distance 0 Rotation Angle 0
emboss "Emboss2" sketch "Sketch8" Depth -2 Horizontal Distance 0 Vertical Distance 0 Rotation Angle 0
emboss "Emboss2" sketch "Sketch8" Depth -2 Horizontal Distance 0 Vertical Distance 0 Rotation Angle 0
work_plane "WorkPlane1" AlongDistance 70
sketch "Sketch1" plane through (0, 0, 1105.5) normal (0, 0, 1) x axis (1, 0, 0)
  line L1 (0, -8.7724) -> (0, 0)
  circle C1 centre (17.5, 0) radius 5
  point P1 (0, 0)
  point P2 (0, 0)
  point P4 (17.5, 0)
  coincident P1 P2
  vertical L1
  horizontal P1 P4
  dimension "d264" diameter C1 = 10
  dimension "d265" distance P1 P4 = 17.5 (= "( 35 / 2 ) * 1 mm")
extrude "Extrude1" new body sketch "Sketch1" profile of C1 along normal blind 170 (= "50 mm + 120 mm")
sketch "Sketch2" plane through (0, 0, 1105.5) normal (0, 0, 1) x axis (1, 0, 0)
chamfer "Chamfer1" distance 3 Rotate Angle 75
fillet "Fillet1" radius 1.5 25
work_plane "WorkPlane2" AlongDistance 5.5
sketch "Sketch3" plane through (0, 5.5, 0) normal (0, 1, 0) x axis (1, 0, 0)
  line L1 (22.5, -1105.5) -> (12.5, -1105.5)
  line L2 (17.5, -1130.5) -> (17.5, -1105.5)
  line L3 (12.5, -1155.5) -> (22.5, -1155.5)
  point P4 (17.5, -1105.5)
  point P3 (22.5, -1105.5)
  point P6 (22.5, -1155.5)
  point P2 (12.5, -1105.5)
  point P7 (12.5, -1155.5)
  point P5 (17.5, -1130.5)
  midpoint L1 P4
  perpendicular L1 L2
  horizontal L3
  vertical P3 P6
  vertical P2 P7
  dimension "d274" distance P4 P5 = 25
  dimension "d280" distance L1 L3 = 50
split_face "SplitFace1"
as_built_joint "As-built7"
rectangular_pattern "00000000-0000-0000-0000-000000000000" uSpaceDistance -35 vSpaceDistance 0
sketch "Sketch1" plane through (0, 0, 1105.5) normal (0, 0, -1) x axis (1, 0, 0)
  circle C1 centre (17.5, 0) radius 5
  circle C2 centre (17.5, 0) radius 5
  circle C3 centre (-17.5, 0) radius 5
  circle C4 centre (-17.5, 0) radius 9
  circle C5 centre (17.5, 0) radius 9
  dimension "d285" = 4
  dimension "d286" = 4
extrude "Extrude1" new body sketch "Sketch1" against normal blind 50 bodies "Preserve1", "Preserve2"
sketch "Sketch2" plane through (0, 0, 1035.5) normal (0, 0, 1) x axis (-1, 0, 0)
  circle C1 centre (0, 0) radius 2.117
  circle C2 centre (-14.1421, 14.1421) radius 2.117
  circle C3 centre (0, 12) radius 2.117
  circle C4 centre (-20, 0) radius 2.117
  circle C5 centre (-8.4853, 8.4853) radius 2.117
  circle C6 centre (-14.1421, -14.1421) radius 2.117
  circle C7 centre (-12, 0) radius 2.117
  circle C8 centre (0, -20) radius 2.117
  circle C9 centre (-8.4853, -8.4853) radius 2.117
  circle C10 centre (14.1421, -14.1421) radius 2.117
  circle C11 centre (0, -12) radius 2.117
  circle C12 centre (20, 0) radius 2.117
  circle C13 centre (8.4853, -8.4853) radius 2.117
  circle C14 centre (14.1421, 14.1421) radius 2.117
  circle C15 centre (12, 0) radius 2.117
  circle C16 centre (0, 20) radius 2.117
  circle C17 centre (8.4853, 8.4853) radius 2.117
  circle C18 centre (0, 0) radius 27.5
  circle C19 centre (-14.1421, 14.1421) radius 2.117
  circle C20 centre (-14.1421, -14.1421) radius 2.117
  circle C21 centre (14.1421, -14.1421) radius 2.117
  circle C22 centre (14.1421, 14.1421) radius 2.117
  circle C23 centre (14.1421, -14.1421) radius 5.117
  circle C24 centre (-14.1421, -14.1421) radius 5.117
  circle C25 centre (-14.1421, 14.1421) radius 5.117
  circle C26 centre (14.1421, 14.1421) radius 5.117
  dimension "d289" = 3
  dimension "d290" = 3
  dimension "d291" = 3
  dimension "d292" = 3
extrude "Extrude2" new body sketch "Sketch2" profile of C2 C6 C10 C14 C19 C20 C21 C22 C23 C24 C25 C26 along normal blind 5 bodies "Preserve3", "Preserve4", "Preserve5", "Preserve6"
as_built_joint "As-built1"
extrude "Extrude3" new body sketch "Sketch2" profile of C2 C6 C10 C14 C19 C20 C21 C22 to an object bodies "Obstacle1", "Obstacle2", "Obstacle3", "Obstacle4"
sketch "Sketch4" plane through (0, 0, 1040.5) normal (0, 0, 1) x axis (-1, 0, 0)
  circle C1 centre (14.1421, -14.1421) radius 2.117
  circle C2 centre (14.1421, -14.1421) radius 5.117
  circle C3 centre (14.1421, -14.1421) radius 5.117
  circle C4 centre (-14.1421, -14.1421) radius 5.117
  circle C5 centre (-14.1421, 14.1421) radius 5.117
  circle C6 centre (14.1421, 14.1421) radius 5.117
extrude "Extrude4" add sketch "Sketch4" along normal blind 50
sketch "Sketch5" plane through (0, 0, 1105.5) normal (0, 0, -1) x axis (1, 0, 0)
  circle C1 centre (17.5, 0) radius 5
  circle C2 centre (17.5, 0) radius 9
  circle C3 centre (17.5, 0) radius 9
  circle C4 centre (-17.5, 0) radius 9
extrude "Extrude5" add sketch "Sketch5" along normal blind 5
step "Screw1"
joint "Assemble1" alignAngle 0 alignOffsetX 0 alignOffsetY 0 alignOffsetZ 0
step "Screw2"
joint "Assemble2" alignAngle 0 alignOffsetX 0 alignOffsetY 0 alignOffsetZ 0
step "Screw3"
joint "Assemble3" alignAngle 0 alignOffsetX 0 alignOffsetY 0 alignOffsetZ 0
step "Screw4"
joint "Assemble4" alignAngle 0 alignOffsetX 0 alignOffsetY 0 alignOffsetZ 0
step "Screw5"
joint "Assemble5" alignAngle 0 alignOffsetX 0 alignOffsetY 0 alignOffsetZ 0
step "Screw6"
joint "Assemble6" alignAngle 0 alignOffsetX 0 alignOffsetY 0 alignOffsetZ 0
step "Screw7"
joint "Assemble7" alignAngle 0 alignOffsetX 0 alignOffsetY 0 alignOffsetZ 0
step "Screw8"
joint "Assemble8" alignAngle 0 alignOffsetX 0 alignOffsetY 0 alignOffsetZ 0
sketch "Sketch1" plane through (0, 0, 1105.5) normal (0, 0, -1) x axis (1, 0, 0)
  circle C1 centre (17.5, 0) radius 5
  circle C2 centre (17.5, 0) radius 5
  circle C3 centre (-17.5, 0) radius 5
  circle C4 centre (-17.5, 0) radius 9
  circle C5 centre (17.5, 0) radius 9
  dimension "d285_1" = 4
  dimension "d286_1" = 4
extrude "Extrude1" new body sketch "Sketch1" against normal blind 50 named "d287_1"
sketch "Sketch2" plane through (0, 0, 1035.5) normal (0, 0, 1) x axis (-1, 0, 0)
  circle C1 centre (0, 0) radius 2.117
  circle C2 centre (-14.1421, 14.1421) radius 2.117
  circle C3 centre (0, 12) radius 2.117
  circle C4 centre (-20, 0) radius 2.117
  circle C5 centre (-8.4853, 8.4853) radius 2.117
  circle C6 centre (-14.1421, -14.1421) radius 2.117
  circle C7 centre (-12, 0) radius 2.117
  circle C8 centre (0, -20) radius 2.117
  circle C9 centre (-8.4853, -8.4853) radius 2.117
  circle C10 centre (14.1421, -14.1421) radius 2.117
  circle C11 centre (0, -12) radius 2.117
  circle C12 centre (20, 0) radius 2.117
  circle C13 centre (8.4853, -8.4853) radius 2.117
  circle C14 centre (14.1421, 14.1421) radius 2.117
  circle C15 centre (12, 0) radius 2.117
  circle C16 centre (0, 20) radius 2.117
  circle C17 centre (8.4853, 8.4853) radius 2.117
  circle C18 centre (0, 0) radius 27.5
  circle C19 centre (-14.1421, 14.1421) radius 2.117
  circle C20 centre (-14.1421, -14.1421) radius 2.117
  circle C21 centre (14.1421, -14.1421) radius 2.117
  circle C22 centre (14.1421, 14.1421) radius 2.117
  circle C23 centre (14.1421, -14.1421) radius 5.117
  circle C24 centre (-14.1421, -14.1421) radius 5.117
  circle C25 centre (-14.1421, 14.1421) radius 5.117
  circle C26 centre (14.1421, 14.1421) radius 5.117
  dimension "d289_1" = 3
  dimension "d290_1" = 3
  dimension "d291_1" = 3
  dimension "d292_1" = 3
extrude "Extrude2" new body sketch "Sketch2" profile of C2 C6 C10 C14 C19 C20 C21 C22 C23 C24 C25 C26 along normal blind 5 named "d293_1" bodies "Connection1", "Connection2", "Connection3", "Connection4"
extrude "Extrude3" new body sketch "Sketch2" profile of C2 C6 C10 C14 C19 C20 C21 C22 to an object bodies "Avoid1", "Avoid2", "Avoid3", "Avoid4"
sketch "Sketch4" plane through (0, 0, 1040.5) normal (0, 0, 1) x axis (-1, 0, 0)
  circle C1 centre (14.1421, -14.1421) radius 2.117
  circle C2 centre (14.1421, -14.1421) radius 5.117
  circle C3 centre (14.1421, -14.1421) radius 5.117
  circle C4 centre (-14.1421, -14.1421) radius 5.117
  circle C5 centre (-14.1421, 14.1421) radius 5.117
  circle C6 centre (14.1421, 14.1421) radius 5.117
extrude "Extrude4" add sketch "Sketch4" along normal blind 50 named "d297_1"
sketch "Sketch5" plane through (0, 0, 1105.5) normal (0, 0, -1) x axis (1, 0, 0)
  circle C1 centre (17.5, 0) radius 5
  circle C2 centre (17.5, 0) radius 9
  circle C3 centre (17.5, 0) radius 9
  circle C4 centre (-17.5, 0) radius 9
extrude "Extrude5" add sketch "Sketch5" along normal blind 5 named "d299_1"
position "Position1" RotateAboutZ -98.9 RotateAboutZ 90 RotateAboutZ -23.6 RotateAboutZ 15
as_built_joint "As-built2"
remove_body "RemoveBody10"
remove_body "RemoveBody11"
base_feature "Base Feature"
sketch "Sketch1" plane through (0, 0, 1105.5) normal (0, 0, -1) x axis (1, 0, 0)
  circle C1 centre (17.5, 0) radius 5
  circle C2 centre (17.5, 0) radius 5
  circle C3 centre (-17.5, 0) radius 5
  circle C4 centre (-17.5, 0) radius 9
  circle C5 centre (17.5, 0) radius 9
  dimension "d285_2" = 4
  dimension "d286_2" = 4
  dimension "d343" OffsetThickness = 2
  dimension "d344" OffsetBlendDistance = 0.872
sketch "Sketch2" plane through (0, 0, 1035.5) normal (0, 0, 1) x axis (-1, 0, 0)
  circle C1 centre (0, 0) radius 2.117
  circle C2 centre (-14.1421, 14.1421) radius 2.117
  circle C3 centre (0, 12) radius 2.117
  circle C4 centre (-20, 0) radius 2.117
  circle C5 centre (-8.4853, 8.4853) radius 2.117
  circle C6 centre (-14.1421, -14.1421) radius 2.117
  circle C7 centre (-12, 0) radius 2.117
  circle C8 centre (0, -20) radius 2.117
  circle C9 centre (-8.4853, -8.4853) radius 2.117
  circle C10 centre (14.1421, -14.1421) radius 2.117
  circle C11 centre (0, -12) radius 2.117
  circle C12 centre (20, 0) radius 2.117
  circle C13 centre (8.4853, -8.4853) radius 2.117
  circle C14 centre (14.1421, 14.1421) radius 2.117
  circle C15 centre (12, 0) radius 2.117
  circle C16 centre (0, 20) radius 2.117
  circle C17 centre (8.4853, 8.4853) radius 2.117
  circle C18 centre (0, 0) radius 27.5
  circle C19 centre (-14.1421, 14.1421) radius 2.117
  circle C20 centre (-14.1421, -14.1421) radius 2.117
  circle C21 centre (14.1421, -14.1421) radius 2.117
  circle C22 centre (14.1421, 14.1421) radius 2.117
  circle C23 centre (14.1421, -14.1421) radius 5.117
  circle C24 centre (-14.1421, -14.1421) radius 5.117
  circle C25 centre (-14.1421, 14.1421) radius 5.117
  circle C26 centre (14.1421, 14.1421) radius 5.117
  dimension "d289_2" = 3
  dimension "d290_2" = 3
  dimension "d291_2" = 3
  dimension "d292_2" = 3
form "Feature1" bodies "Body15"
base_feature "Feature" bodies "Preserve1 (1)", "Preserve2 (1)", "Preserve3 (1)", "Preserve4 (1)", "Preserve5 (1)", "Preserve6 (1)"
form "Feature2" bodies "Body17", "Body18", "Body18 (1)"
boundary_fill "BoundaryFill1"
joint "Assemble9" alignAngle 180 alignOffsetX 0 alignOffsetY 0 alignOffsetZ 0
remove_body "RemoveBody10"
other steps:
fillet "Fillet1" radius 10
thread "Thread1" ThreadOffset 0 ThreadDepth 7.4
thread "Thread2" ThreadOffset 0 ThreadDepth 7.4
thread "Thread3" ThreadOffset 0 ThreadDepth 7.4
hole "Hole2" HoleDepth 20 HoleDiameter 4.234 TipAngle 180
thread "Thread1" ThreadOffset 0 ThreadDepth 7.4
hole "Hole3" HoleDepth 20 HoleDiameter 4.234 TipAngle 180
thread "Thread2" ThreadOffset 0 ThreadDepth 7.4
revolve "Revolve2" sketch "Sketch5" AlongAngle 360
create_component "CreateComponent1"
create_component "CreateComponent2"
create_component "CreateComponent3"
create_component "CreateComponent4"
create_component "CreateComponent5"
create_component "CreateComponent6"
create_component "CreateComponent7"
create_component "CreateComponent8"
create_component "CreateComponent1"
create_component "CreateComponent2"
joint_origin "JointOrigin1"
joint_origin "JointOrigin2"
joint_origin "JointOrigin3"
joint_origin "JointOrigin4"
joint_origin "JointOrigin5"
joint_origin "JointOrigin6"
joint_origin "JointOrigin7"
joint_origin "JointOrigin8"
create_component "CreateComponent3"
remove_body "RemoveBody1"
remove_body "RemoveBody2"
remove_body "RemoveBody3"
remove_body "RemoveBody4"
remove_body "RemoveBody5"
remove_body "RemoveBody6"
remove_body "RemoveBody7"
remove_body "RemoveBody8"
remove_body "RemoveBody9"
create_component "CreateComponent4"
joint_origin "JointOrigin1"
joint_origin "JointOrigin9"
named bodies: "Preserve1", "Preserve2", "Preserve3", "Preserve4", "Preserve5", "Preserve6", "Obstacle1", "Obstacle2", "Obstacle3", "Obstacle4", "Connection1", "Connection2", "Connection3", "Connection4", "Avoid1", "Avoid2", "Avoid3", "Avoid4", "Body15", "Preserve1 (1)", "Preserve2 (1)", "Preserve3 (1)", "Preserve4 (1)", "Preserve5 (1)", "Preserve6 (1)", "Body17", "Body18", "Body18 (1)"

design "Broached Hexagon Socket Head Cap Screw ASME B18.3.1M - M5x0.8 x 8 Steel Grade 2 Plain"
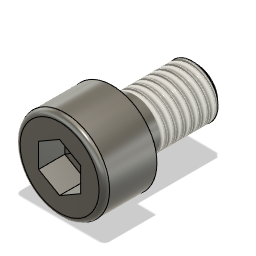
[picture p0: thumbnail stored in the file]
description: Broached Hexagon Socket Head Cap Screw ASME B18.3.1M - M5x0.8 x 8
part number: arrangementsContainer
parameter "adsk_nomlen" = 8
parameter "adsk_headh" = 5
parameter "adsk_headdia" = 8.5
parameter "adsk_nomdia" = 5
parameter "adsk_philwidth" = 4
parameter "adsk_phildepth" = 2.5
parameter "adsk_thrlen" = 5.9092
parameter "adsk_startlen" = 0.4908
parameter "adsk_endpointdia" = 4.0185
sketch "Sketch1" plane through (0, 0, 0) normal (0, 1, 0) x axis (1, 0, 0)
  line L1 (-2.5, 8) -> (-2.5, 0)
  line L2 (0, 8) -> (-2.5, 8)
  line L3 (0, -5) -> (0, 8)
  line L4 (-4.25, 0) -> (-2.5, 0)
  line L5 (-4.25, -5) -> (-4.25, 0)
  line L6 (0, -5) -> (-4.25, -5)
  point P1 (0, 0)
  point P4 (0, 8)
  point P7 (0, -5)
  point P5 (-4.25, 0)
  point P6 (-4.25, -5)
  perpendicular L1 L2
  collinear P1 P4 P7
  perpendicular L1 L4
  coincident P1 L4
  vertical L1
  vertical L3
  parallel L3 L5
  coincident L3 P7
  perpendicular L3 L6
  dimension "d9" = 5 (= "adsk_nomdia")
  dimension "d66" = 8.5 (= "adsk_headdia")
  dimension "d68" distance P1 P4 = 8 (= "adsk_nomlen")
  dimension "d79" distance P5 P6 = 5 (= "adsk_headh")
revolve "Revolve1" sketch "Sketch1" AlongAngle 360
work_plane "WorkPlane1" AlongDistance 5 (= "adsk_headh")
